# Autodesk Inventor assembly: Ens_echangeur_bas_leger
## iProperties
Shininess: 64.0
Length Units: 11269
Angle Units: 11279
Time Units: 11290
Mass Units: 11283
Length Display Precision: 3
Angle Display Precision: 2
Compacted: True
Created: 2008-03
Part Number: Ens_echangeur_bas_leger
Document SubType Name: Assembly
Designer: Pascal
Density: 0.0
Volumn: 0.0
Area: 0.0
PropertySet Name: Model Information
Control State: 0
Master: False
Checked Out: False
DESIGNATION: Echangeur bas
Author: Pascal
